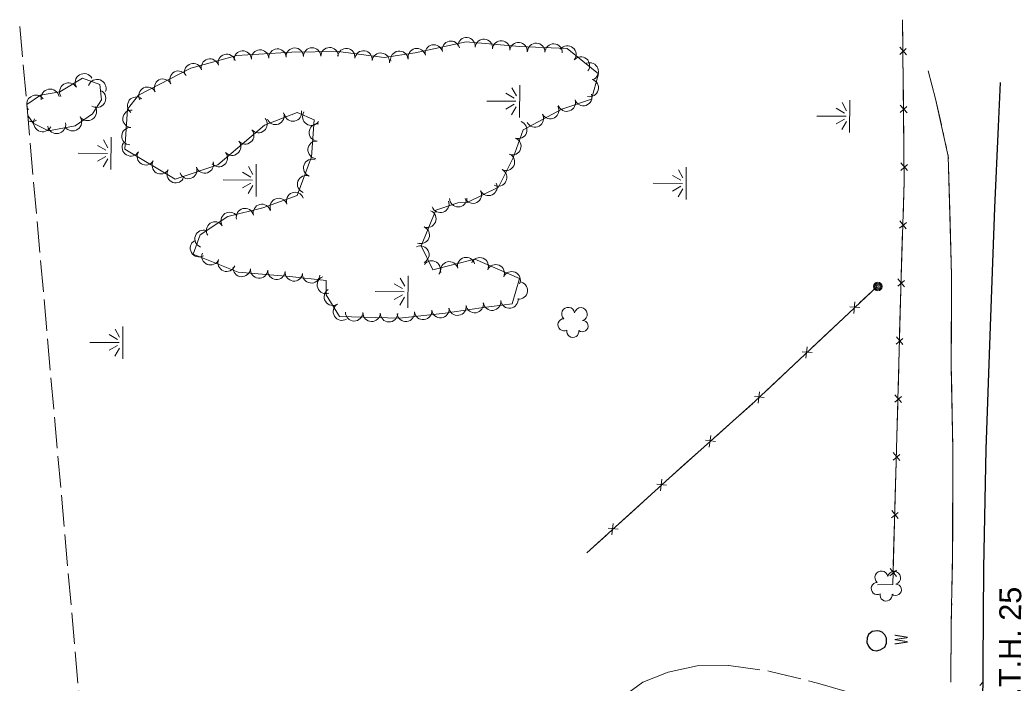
# Model space of a CAD drawing. Extents: x 296583 to 298831, y 44522 to 45957.
# Drawn here: x 297236.9 to 297692.9, y 45555.3 to 45859.1 of the extents above; entities that cross this region are included whole.
import ezdxf

# ---------------------------------------------------------------- set-up
doc = ezdxf.new("R2010")
doc.units = 0
doc.header["$LTSCALE"] = 2.4
doc.linetypes.add('LONG_DASHED', pattern=[7.5, 6, -1.5])
for name, color, linetype, lineweight in [('11', 7, 'Continuous', 25), ('14', 7, 'Continuous', 13), ('15', 7, 'Continuous', 13), ('17', 7, 'LONG_DASHED', 13), ('18', 7, 'Continuous', 13), ('19', 7, 'Continuous', 13), ('4', 7, 'Continuous', 13)]:
    doc.layers.add(name, color=color, linetype=linetype, lineweight=lineweight)

msp = doc.modelspace()

# ---------------------------------------------------------------- linework, layer by layer
at = {"layer": '11'}
msp.add_lwpolyline([(297677.324, 45228.283), (297677.318, 45281.197), (297677.332, 45323.688), (297677.669, 45372.563), (297677.785, 45423.877), (297677.961, 45473.565), (297678.391, 45519.767), (297678.595, 45564.143), (297678.918, 45607.954), (297680.057, 45662.442), (297681.8, 45714.535), (297683.993, 45772.961), (297685.684, 45810.311), (297686.569, 45830.443)], dxfattribs=at)
at = {"layer": '14'}
for centre, radius in [((297630.363, 45736.966), 2.018), ((297630.35, 45736.963), 1.518), ((297630.39, 45736.969), 1.008), ((297630.38, 45736.973), 0.502)]:
    msp.add_circle(centre, radius, dxfattribs=at)
at = {"layer": '15'}
for p, q in [((297641.796, 45848.341), (297641.689, 45859.135)), ((297643.505, 45843.188), (297640.382, 45846.701)), ((297640.415, 45843.319), (297643.412, 45846.015)), ((297641.952, 45832.572), (297641.858, 45842.065)), ((297642.059, 45821.778), (297641.952, 45832.572)), ((297643.768, 45816.625), (297640.645, 45820.138)), ((297640.678, 45816.756), (297643.675, 45819.452)), ((297642.215, 45806.009), (297642.121, 45815.502)), ((297642.322, 45795.215), (297642.215, 45806.009)), ((297644.031, 45790.062), (297640.908, 45793.575)), ((297640.941, 45790.193), (297643.938, 45792.889)), ((297641.916, 45768.659), (297642.253, 45779.448)), ((297640.329, 45763.698), (297643.435, 45766.268)), ((297643.411, 45763.44), (297640.435, 45767.079)), ((297641.423, 45752.897), (297641.719, 45762.386)), ((297641.085, 45742.107), (297641.423, 45752.897)), ((297629.854, 45736.825), (297622.029, 45729.462)), ((297639.517, 45737.14), (297642.611, 45739.724)), ((297642.6, 45736.895), (297639.608, 45740.521)), ((297640.659, 45726.343), (297640.913, 45735.834)), ((297622.093, 45727.3), (297617.551, 45727.724)), ((297619.831, 45729.971), (297619.305, 45724.677)), ((297616.856, 45724.595), (297607.959, 45716.223)), ((297640.37, 45715.553), (297640.659, 45726.343)), ((297607.959, 45716.223), (297600.134, 45708.86)), ((297641.889, 45710.34), (297638.897, 45713.966)), ((297597.937, 45709.369), (297597.411, 45704.075)), ((297638.806, 45710.585), (297641.9, 45713.169)), ((297600.198, 45706.698), (297595.656, 45707.122)), ((297639.948, 45699.788), (297640.202, 45709.279)), ((297594.962, 45703.993), (297586.065, 45695.621)), ((297639.659, 45688.998), (297639.948, 45699.788)), ((297586.065, 45695.621), (297578.239, 45688.258)), ((297576.042, 45688.767), (297575.516, 45683.472)), ((297638.096, 45684.03), (297641.189, 45686.614)), ((297641.179, 45683.785), (297638.186, 45687.411)), ((297573.04, 45683.42), (297563.92, 45675.292)), ((297578.303, 45686.095), (297573.761, 45686.52)), ((297639.237, 45673.233), (297639.491, 45682.724)), ((297563.92, 45675.292), (297555.898, 45668.143)), ((297553.715, 45668.711), (297553.046, 45663.433)), ((297555.904, 45665.98), (297551.375, 45666.527)), ((297550.596, 45663.418), (297541.476, 45655.29)), ((297637.369, 45657.478), (297640.466, 45660.057)), ((297640.451, 45657.228), (297637.464, 45660.858)), ((297638.494, 45646.679), (297638.763, 45656.17)), ((297533.494, 45645.966), (297528.959, 45646.465)), ((297531.276, 45648.674), (297530.663, 45643.389)), ((297638.189, 45635.889), (297638.494, 45646.679)), ((297528.213, 45643.347), (297519.179, 45635.124)), ((297519.179, 45635.124), (297511.233, 45627.891)), ((297636.618, 45630.924), (297639.716, 45633.503)), ((297639.701, 45630.674), (297636.714, 45634.304)), ((297509.044, 45628.436), (297508.431, 45623.151)), ((297637.744, 45620.126), (297638.012, 45629.616)), ((297505.981, 45623.11), (297496.947, 45614.886)), ((297511.262, 45625.728), (297506.727, 45626.227)), ((297637.439, 45609.335), (297637.744, 45620.126)), ((297635.868, 45604.37), (297638.965, 45606.949)), ((297638.95, 45604.121), (297635.963, 45607.751))]:
    msp.add_line(p, q, dxfattribs=at)
for points in [[(297630.268, 45600.322), (297637.189, 45600.492), (297639.106, 45668.324), (297641.055, 45741.146), (297642.424, 45784.913), (297641.689, 45859.135)], [(297642.253, 45779.448), (297642.424, 45784.913), (297642.384, 45788.939)], [(297629.854, 45736.825), (297574.146, 45684.406), (297534.628, 45649.187), (297496.947, 45614.886)], [(297638.94, 45662.443), (297639.106, 45668.324), (297639.237, 45673.233)], [(297541.476, 45655.29), (297534.628, 45649.187), (297533.465, 45648.129)], [(297630.268, 45600.322), (297637.189, 45600.492), (297637.262, 45603.062)]]:
    msp.add_lwpolyline(points, dxfattribs=at)
at = {"layer": '15', "lineweight": 25}
for points in [[(297630.004, 45579.243), (297627.722, 45578.881), (297626.106, 45577.535), (297625.438, 45575.985), (297625.287, 45573.854), (297626.016, 45572.264), (297626.912, 45571.153), (297627.441, 45570.776), (297628.016, 45570.378), (297629.818, 45570.084)], [(297629.818, 45570.084), (297631.484, 45570.44), (297633.552, 45571.721), (297634.269, 45573.594), (297634.36, 45575.798), (297633.588, 45577.424), (297632.335, 45578.623), (297631.101, 45579.089), (297630.004, 45579.243)]]:
    msp.add_lwpolyline(points, dxfattribs=at)
at = {"layer": '17'}
for points in [[(297513.988, 45549.38), (297522.671, 45555.645), (297534.158, 45560.284), (297547.548, 45563.214), (297562.032, 45563.351), (297581.047, 45560.657), (297602.708, 45555.307), (297621.88, 45549.662)], [(297677.156, 45554.105), (297678.556, 45555.63)]]:
    msp.add_lwpolyline(points, dxfattribs=at)
at = {"layer": '18'}
msp.add_lwpolyline([(297441.988, 45775.421), (297456.428, 45782.568), (297463.088, 45795.948), (297467.711, 45808.766), (297485.417, 45818.23), (297499.045, 45822.829), (297502.276, 45834.442), (297487.914, 45846.058), (297466.06, 45846.887), (297441.658, 45849.157), (297418.176, 45844.026), (297403.986, 45841.918), (297382.823, 45844.648), (297361.639, 45844.341), (297336.464, 45842.886), (297315.272, 45837.005), (297291.381, 45824.632), (297286.365, 45818.292), (297285.131, 45799.908), (297308.185, 45786.155), (297327.723, 45792.708), (297349.041, 45810.953), (297364.162, 45816.699), (297371.9, 45813.324), (297370.677, 45796.427), (297364.052, 45778.705), (297348.339, 45772.957), (297332.3, 45769.004), (297319.58, 45760.606), (297316.407, 45751.756), (297337.082, 45743.486), (297360.676, 45741.579), (297377.404, 45739.688), (297377.452, 45733.173), (297383.502, 45723.253), (297410.983, 45722.503), (297431.917, 45724.748), (297448.484, 45727.267), (297462.671, 45729.051), (297466.006, 45740.579), (297445.597, 45749.483), (297426.335, 45744.65), (297420.995, 45755.565), (297427.648, 45771.902), (297437.797, 45775.349)], close=True, dxfattribs=at)
for points in [[(297250.13, 45808.251), (297262.309, 45810.614), (297270.287, 45816.072), (297274.341, 45822.488), (297273.657, 45829.537), (297265.691, 45832.457), (297255.22, 45826.253), (297246.39, 45824.719), (297240.208, 45820.333), (297240.218, 45819.153)], [(297240.555, 45815.346), (297242.997, 45811.754), (297250.13, 45808.251)]]:
    msp.add_lwpolyline(points, dxfattribs=at)
for centre, radius, start, end in [((297441.746, 45847.049), 3.994, 354.69301, 174.67769), ((297362.979, 45842.27), 3.994, 0.83794, 180.82262), ((297370.966, 45842.385), 3.994, 0.83794, 180.82262), ((297378.953, 45842.501), 3.994, 0.83794, 180.82262), ((297426.773, 45843.765), 3.994, 12.33351, 192.31818), ((297434.577, 45845.47), 3.994, 12.33351, 192.31818), ((297449.699, 45846.309), 3.994, 354.69301, 174.67769), ((297457.653, 45845.569), 3.994, 354.69301, 174.67769), ((297465.606, 45844.83), 3.994, 354.69301, 174.67769), ((297473.702, 45844.505), 3.994, 357.83527, 177.81995), ((297481.684, 45844.202), 3.994, 357.83527, 177.81995), ((297488.024, 45843.28), 3.994, 321.04169, 141.02637), ((297331.796, 45839.421), 3.994, 15.51755, 195.50223), ((297339.144, 45840.947), 3.994, 3.31542, 183.30009), ((297347.119, 45841.408), 3.994, 3.31542, 183.30009), ((297355.093, 45841.869), 3.994, 3.31542, 183.30009), ((297386.61, 45842.052), 3.994, 352.65717, 172.64185), ((297394.532, 45841.03), 3.994, 352.65717, 172.64185), ((297402.454, 45840.008), 3.994, 352.65717, 172.64185), ((297410.933, 45840.836), 3.994, 8.45746, 188.44214), ((297418.969, 45842.059), 3.994, 12.33351, 192.31818), ((297494.235, 45838.257), 3.994, 321.04169, 141.02637), ((297316.402, 45835.149), 3.994, 15.51755, 195.50223), ((297324.099, 45837.285), 3.994, 15.51755, 195.50223), ((297498.23, 45835.531), 3.994, 291.04169, 111.02637), ((297266.43, 45830.369), 4.151, 30.65413, 210.63881), ((297309.667, 45831.748), 3.994, 27.38702, 207.3717), ((297259.288, 45826.138), 4.151, 30.65413, 210.63881), ((297272.335, 45827.708), 4.151, 339.87685, 159.86153), ((297295.481, 45824.401), 3.994, 27.38702, 207.3717), ((297302.574, 45828.074), 3.994, 27.38702, 207.3717), ((297498.299, 45827.946), 3.994, 254.45989, 74.44457), ((297244.222, 45820.517), 4.151, 35.36257, 176.875), ((297250.803, 45823.281), 4.151, 9.86306, 189.84774), ((297272.18, 45823.135), 4.151, 237.72059, 57.70527), ((297290.257, 45819.842), 3.994, 51.65777, 231.64245), ((297495.289, 45823.768), 3.994, 198.6555, 18.64018), ((297244.222, 45820.517), 4.151, 193.24773, 215.34724), ((297267.972, 45817.12), 4.151, 214.38492, 34.36959), ((297480.153, 45817.787), 3.994, 208.13252, 28.1172), ((297487.721, 45821.214), 3.994, 198.6555, 18.64018), ((297261.12, 45812.433), 4.151, 214.38492, 34.36959), ((297288.159, 45813.805), 3.994, 86.16752, 266.1522), ((297354.164, 45815.136), 3.994, 200.81452, 20.7992), ((297362.155, 45816.664), 3.994, 190.81452, 10.7992), ((297370.554, 45814.783), 3.994, 146.44279, 326.42747), ((297473.109, 45814.022), 3.994, 208.13252, 28.1172), ((297242.262, 45816.701), 4.151, 249.06904, 304.19564), ((297247.363, 45812.031), 4.151, 153.85211, 333.83679), ((297253.791, 45811.175), 4.151, 190.98791, 10.97258), ((297287.624, 45805.835), 3.994, 86.16752, 266.1522), ((297346.38, 45811.427), 3.994, 220.56621, 40.55089), ((297373.579, 45807.568), 3.994, 85.86783, 265.85251), ((297465.49, 45808.77), 3.994, 250.17508, 70.15976), ((297340.311, 45806.233), 3.994, 220.56621, 40.55089), ((297287.84, 45800.726), 3.994, 149.18922, 329.1739), ((297334.242, 45801.039), 3.994, 220.56621, 40.55089), ((297373.003, 45799.601), 3.994, 85.86783, 265.85251), ((297462.78, 45801.255), 3.994, 250.17508, 70.15976), ((297294.7, 45796.634), 3.994, 149.18922, 329.1739), ((297328.174, 45795.846), 3.994, 220.56621, 40.55089), ((297459.835, 45794.105), 3.994, 243.54547, 63.53015), ((297301.56, 45792.541), 3.994, 149.18922, 329.1739), ((297314.171, 45790.368), 3.994, 198.54899, 18.53367), ((297321.744, 45792.908), 3.994, 198.54899, 18.53367), ((297371.005, 45791.335), 3.994, 69.51045, 249.49513), ((297308.42, 45788.449), 3.994, 149.18922, 329.1739), ((297368.208, 45783.853), 3.994, 69.51045, 249.49513), ((297456.276, 45786.954), 3.994, 243.54547, 63.53015), ((297451.8, 45782.61), 3.994, 206.34052, 26.3252), ((297363.164, 45776.154), 3.994, 20.10077, 200.08545), ((297444.641, 45779.067), 3.994, 206.34052, 26.3252), ((297347.912, 45770.699), 3.994, 13.85294, 193.83762), ((297355.662, 45773.41), 3.994, 20.10077, 200.08545), ((297429.749, 45774.823), 3.994, 198.76717, 18.75185), ((297437.959, 45777.443), 3.994, 180.99189, 0.97656), ((297333.108, 45767.032), 3.994, 33.44126, 213.42594), ((297340.156, 45768.787), 3.994, 13.85294, 193.83762), ((297423.804, 45768.005), 3.994, 247.84978, 67.83446), ((297326.442, 45762.631), 3.994, 33.44126, 213.42594), ((297420.791, 45760.607), 3.994, 247.84978, 67.83446), ((297321.161, 45758.822), 3.994, 70.28333, 250.26801), ((297319.06, 45754.531), 3.994, 120.28333, 300.26801), ((297420.609, 45751.597), 3.994, 296.07716, 116.06184), ((297324.351, 45750.83), 3.994, 158.20625, 338.19093), ((297331.767, 45747.864), 3.994, 158.20625, 338.19093), ((297425.77, 45744.803), 3.994, 326.07716, 146.06184), ((297433.846, 45744.379), 3.994, 14.09289, 194.07756), ((297441.594, 45746.323), 3.994, 14.09289, 194.07756), ((297447.819, 45746.233), 3.994, 336.43707, 156.42175), ((297455.14, 45743.039), 3.994, 336.43707, 156.42175), ((297338.673, 45745.455), 3.994, 175.38674, 355.37142), ((297346.635, 45744.811), 3.994, 175.38674, 355.37142), ((297354.597, 45744.168), 3.994, 175.38674, 355.37142), ((297362.62, 45743.463), 3.994, 173.5581, 353.54278), ((297370.557, 45742.566), 3.994, 173.5581, 353.54278), ((297377.242, 45737.694), 3.994, 110.42979, 290.41446), ((297462.462, 45739.844), 3.994, 336.43707, 156.42175), ((297465.707, 45735.172), 3.994, 263.87274, 83.85741), ((297380.452, 45732.269), 3.994, 121.3858, 301.37048), ((297384.611, 45725.449), 3.994, 121.3858, 301.37048), ((297437.606, 45727.728), 3.994, 188.65322, 8.6379), ((297445.503, 45728.928), 3.994, 188.65322, 8.6379), ((297453.472, 45730.001), 3.994, 187.17492, 7.1596), ((297461.398, 45730.998), 3.994, 187.17492, 7.1596), ((297390.247, 45725.16), 3.994, 178.44436, 358.42904), ((297398.232, 45724.942), 3.994, 178.44436, 358.42904), ((297406.217, 45724.724), 3.994, 178.44436, 358.42904), ((297413.905, 45724.919), 3.994, 186.12877, 6.11345), ((297421.847, 45725.771), 3.994, 186.12877, 6.11345), ((297429.789, 45726.622), 3.994, 186.12877, 6.11345), ((297488.343, 45724.487), 2.974, 7.98733, 229.22121), ((297494.195, 45724.331), 2.975, 285.63814, 168.61141), ((297486.447, 45719.459), 2.777, 90.95822, 298.73121), ((297494.918, 45718.857), 2.611, 230.34337, 88.27598), ((297490.5, 45716.428), 2.783, 167.63523, 8.64628), ((297631.976, 45603.674), 2.974, 7.98733, 229.22121), ((297637.828, 45603.518), 2.975, 285.63814, 168.61141), ((297630.08, 45598.646), 2.777, 90.95822, 298.73121), ((297638.551, 45598.044), 2.611, 230.34337, 88.27598), ((297634.133, 45595.615), 2.783, 167.63523, 8.64628)]:
    msp.add_arc(centre, radius, start, end, dxfattribs=at)
at = {"layer": '19'}
for p, q in [((297462.547, 45828.065), (297464.609, 45824.364)), ((297466.018, 45814.398), (297466.13, 45829.192)), ((297463.665, 45823.271), (297459.832, 45825.5)), ((297451.005, 45821.937), (297464.424, 45821.835)), ((297463.644, 45820.466), (297459.777, 45818.295)), ((297462.452, 45815.69), (297464.57, 45819.359)), ((297613.959, 45821.22), (297616.021, 45817.519)), ((297617.43, 45807.553), (297617.542, 45822.347)), ((297602.417, 45815.092), (297615.836, 45814.99)), ((297615.077, 45816.426), (297611.244, 45818.655)), ((297615.056, 45813.621), (297611.189, 45811.45)), ((297613.864, 45808.845), (297615.982, 45812.514)), ((297278.717, 45790.553), (297278.829, 45805.347)), ((297660.636, 45805.888), (297660.253, 45807.603)), ((297276.364, 45799.426), (297272.531, 45801.655)), ((297275.246, 45804.22), (297277.308, 45800.519)), ((297661.784, 45800.744), (297661.401, 45802.458)), ((297263.704, 45798.092), (297277.123, 45797.99)), ((297276.343, 45796.621), (297272.476, 45794.45)), ((297275.151, 45791.845), (297277.269, 45795.514)), ((297341.779, 45791.925), (297343.841, 45788.224)), ((297345.25, 45778.258), (297345.362, 45793.052)), ((297542.424, 45776.816), (297542.536, 45791.61)), ((297663.489, 45766.586), (297662.808, 45792.058)), ((297342.897, 45787.131), (297339.064, 45789.36)), ((297540.071, 45785.689), (297536.238, 45787.918)), ((297538.953, 45790.483), (297541.015, 45786.782)), ((297330.237, 45785.797), (297343.656, 45785.695)), ((297342.876, 45784.326), (297339.009, 45782.155)), ((297341.684, 45779.55), (297343.802, 45783.219)), ((297527.411, 45784.355), (297540.83, 45784.253)), ((297540.05, 45782.884), (297536.183, 45780.713)), ((297538.858, 45778.108), (297540.976, 45781.777)), ((297414.811, 45727.14), (297414.923, 45741.934)), ((297412.458, 45736.013), (297408.625, 45738.242)), ((297411.34, 45740.807), (297413.402, 45737.106)), ((297664.118, 45735.838), (297664.125, 45737.596)), ((297399.798, 45734.679), (297413.217, 45734.577)), ((297412.437, 45733.208), (297408.57, 45731.037)), ((297664.099, 45730.564), (297664.106, 45732.322)), ((297411.245, 45728.432), (297413.363, 45732.101)), ((297664.081, 45725.29), (297664.087, 45727.048)), ((297284.104, 45703.84), (297284.216, 45718.634)), ((297281.751, 45712.713), (297277.918, 45714.942)), ((297280.633, 45717.507), (297282.695, 45713.806)), ((297269.091, 45711.379), (297282.51, 45711.277)), ((297281.73, 45709.908), (297277.863, 45707.737)), ((297280.538, 45705.132), (297282.656, 45708.801)), ((297664.62, 45670.796), (297664.067, 45696.283)), ((297664.734, 45665.522), (297664.696, 45667.28)), ((297664.804, 45660.249), (297664.809, 45662.007)), ((297664.789, 45654.974), (297664.794, 45656.732)), ((297664.709, 45625.963), (297664.78, 45651.457)), ((297664.311, 45595.197), (297664.345, 45596.955)), ((297664.208, 45589.923), (297664.243, 45591.681)), ((297664.106, 45584.649), (297664.14, 45586.407)), ((297663.904, 45555.643), (297664.053, 45581.133))]:
    msp.add_line(p, q, dxfattribs=at)
for points in [[(297663.904, 45555.643), (297664.059, 45582.244), (297664.676, 45613.972), (297664.809, 45662.058), (297663.99, 45699.858), (297664.141, 45742.203), (297662.683, 45796.717), (297656.816, 45822.998), (297653.433, 45835.781)], [(297659.487, 45811.033), (297656.816, 45822.998), (297653.433, 45835.781)], [(297662.714, 45795.571), (297662.683, 45796.717), (297662.55, 45797.314)], [(297664.137, 45741.112), (297664.141, 45742.203), (297663.489, 45766.586)], [(297664.067, 45696.283), (297663.99, 45699.858), (297664.068, 45721.774)], [(297664.413, 45600.471), (297664.676, 45613.972), (297664.709, 45625.963)]]:
    msp.add_lwpolyline(points, dxfattribs=at)
at = {"layer": '4', "linetype": 'LONG_DASHED'}
msp.add_line((297342.991, 44658.77), (297236.947, 45856.087), dxfattribs=at)

# ---------------------------------------------------------------- texts
at = {"layer": '11', "width": 1.05}
msp.add_text('S.T.H. 25', height=10, rotation=89.626, dxfattribs=at).set_placement((297695.769, 45540.099))
at = {"layer": '15', "width": 0.6}
msp.add_text('W', height=6, rotation=89.564, dxfattribs=at).set_placement((297644.091, 45572.89))

doc.saveas('drawing.dxf')
